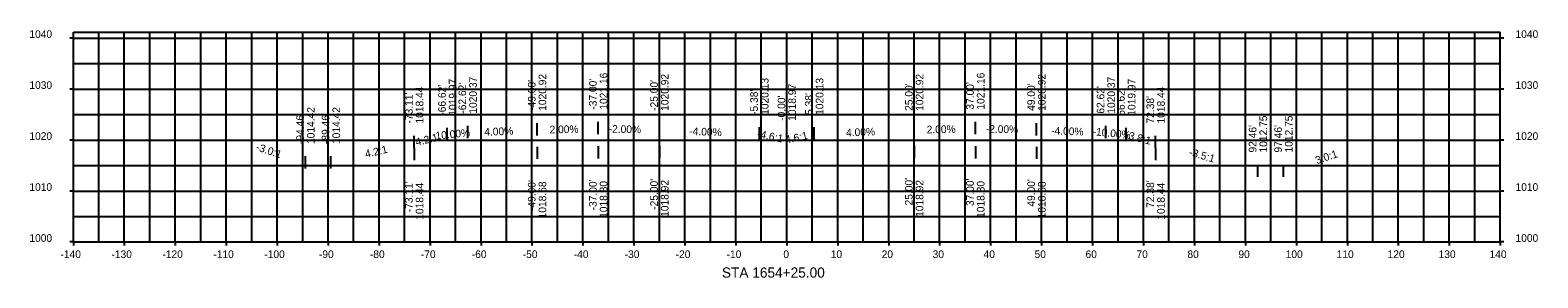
# Model space of a CAD drawing. Extents: x -148 to 147, y 993 to 1042.
import ezdxf

# ---------------------------------------------------------------- set-up
doc = ezdxf.new("R2010")
doc.units = 0
for name, color, linetype in [('SheetBorder', 7, 'Continuous'), ('SheetGridMajor', 7, 'Continuous'), ('SheetGridMinor', 7, 'Continuous'), ('SheetText', 7, 'Continuous'), ('Text', 7, 'Continuous')]:
    doc.layers.add(name, color=color, linetype=linetype)

msp = doc.modelspace()

# ---------------------------------------------------------------- linework, layer by layer
at = {"layer": 'SheetBorder'}
for p, q in [((-140, 1041.16), (140, 1041.16)), ((-140, 1000), (-140, 1041.16)), ((140, 1000), (140, 1041.16)), ((-140, 1000), (140, 1000))]:
    msp.add_line(p, q, dxfattribs=at)
at = {"layer": 'SheetGridMajor'}
for p, q in [((-140, 1040), (-140.72, 1040)), ((-140, 1040), (140, 1040)), ((-130, 1000), (-130, 1041.16)), ((-120, 1000), (-120, 1041.16)), ((-110, 1000), (-110, 1041.16)), ((-100, 1000), (-100, 1041.16)), ((-90, 1000), (-90, 1041.16)), ((-80, 1000), (-80, 1041.16)), ((-70, 1000), (-70, 1041.16)), ((-60, 1000), (-60, 1041.16)), ((-50, 1000), (-50, 1041.16)), ((-40, 1000), (-40, 1041.16)), ((-30, 1000), (-30, 1041.16)), ((-20, 1000), (-20, 1041.16)), ((-10, 1000), (-10, 1041.16)), ((0, 1000), (0, 1041.16)), ((10, 1000), (10, 1041.16)), ((20, 1000), (20, 1041.16)), ((30, 1000), (30, 1041.16)), ((40, 1000), (40, 1041.16)), ((50, 1000), (50, 1041.16)), ((60, 1000), (60, 1041.16)), ((70, 1000), (70, 1041.16)), ((80, 1000), (80, 1041.16)), ((90, 1000), (90, 1041.16)), ((100, 1000), (100, 1041.16)), ((110, 1000), (110, 1041.16)), ((120, 1000), (120, 1041.16)), ((130, 1000), (130, 1041.16)), ((140.72, 1040), (140, 1040)), ((-140, 1030), (-140.72, 1030)), ((-140, 1030), (140, 1030)), ((140.72, 1030), (140, 1030)), ((-140, 1020), (-140.72, 1020)), ((-140, 1020), (140, 1020)), ((140.72, 1020), (140, 1020)), ((-140, 1010), (-140.72, 1010)), ((-140, 1010), (140, 1010)), ((140.72, 1010), (140, 1010)), ((-140, 1000), (-140.72, 1000)), ((-140, 1000), (-140, 999.28)), ((-130, 1000), (-130, 999.28)), ((-120, 1000), (-120, 999.28)), ((-110, 1000), (-110, 999.28)), ((-100, 1000), (-100, 999.28)), ((-90, 1000), (-90, 999.28)), ((-80, 1000), (-80, 999.28)), ((-70, 1000), (-70, 999.28)), ((-60, 1000), (-60, 999.28)), ((-50, 1000), (-50, 999.28)), ((-40, 1000), (-40, 999.28)), ((-30, 1000), (-30, 999.28)), ((-20, 1000), (-20, 999.28)), ((-10, 1000), (-10, 999.28)), ((0, 1000), (0, 999.28)), ((10, 1000), (10, 999.28)), ((20, 1000), (20, 999.28)), ((30, 1000), (30, 999.28)), ((40, 1000), (40, 999.28)), ((50, 1000), (50, 999.28)), ((60, 1000), (60, 999.28)), ((70, 1000), (70, 999.28)), ((80, 1000), (80, 999.28)), ((90, 1000), (90, 999.28)), ((100, 1000), (100, 999.28)), ((110, 1000), (110, 999.28)), ((120, 1000), (120, 999.28)), ((130, 1000), (130, 999.28)), ((140, 1000), (140, 999.28)), ((140.72, 1000), (140, 1000))]:
    msp.add_line(p, q, dxfattribs=at)
at = {"layer": 'SheetGridMinor'}
for p, q in [((-135, 1000), (-135, 1041.16)), ((-125, 1000), (-125, 1041.16)), ((-115, 1000), (-115, 1041.16)), ((-105, 1000), (-105, 1041.16)), ((-95, 1000), (-95, 1041.16)), ((-85, 1000), (-85, 1041.16)), ((-75, 1000), (-75, 1041.16)), ((-65, 1000), (-65, 1041.16)), ((-55, 1000), (-55, 1041.16)), ((-45, 1000), (-45, 1041.16)), ((-35, 1000), (-35, 1041.16)), ((-25, 1000), (-25, 1041.16)), ((-15, 1000), (-15, 1041.16)), ((-5, 1000), (-5, 1041.16)), ((5, 1000), (5, 1041.16)), ((15, 1000), (15, 1041.16)), ((25, 1000), (25, 1041.16)), ((35, 1000), (35, 1041.16)), ((45, 1000), (45, 1041.16)), ((55, 1000), (55, 1041.16)), ((65, 1000), (65, 1041.16)), ((75, 1000), (75, 1041.16)), ((85, 1000), (85, 1041.16)), ((95, 1000), (95, 1041.16)), ((105, 1000), (105, 1041.16)), ((115, 1000), (115, 1041.16)), ((125, 1000), (125, 1041.16)), ((135, 1000), (135, 1041.16)), ((-140, 1035), (140, 1035)), ((-140, 1025), (140, 1025)), ((-140, 1015), (140, 1015)), ((-140, 1005), (140, 1005))]:
    msp.add_line(p, q, dxfattribs=at)
at = {"layer": 'Text'}
for p, q in [((-73.11, 1018.44), (-73.11, 1020.84)), ((-66.62, 1019.97), (-66.62, 1022.37)), ((-62.62, 1020.37), (-62.62, 1022.77)), ((-49, 1020.92), (-49, 1023.32)), ((-37, 1021.16), (-37, 1023.56)), ((-37, 1021.16), (-37, 1023.56)), ((-25, 1020.92), (-25, 1023.32)), ((-5.38, 1020.13), (-5.38, 1022.53)), ((0, 1018.97), (0, 1021.37)), ((5.38, 1020.13), (5.38, 1022.53)), ((25, 1020.92), (25, 1023.32)), ((37, 1021.16), (37, 1023.56)), ((49, 1020.92), (49, 1023.32)), ((62.62, 1020.37), (62.62, 1022.77)), ((66.62, 1019.97), (66.62, 1022.37)), ((72.38, 1018.44), (72.38, 1020.84)), ((72.38, 1018.44), (72.38, 1020.84)), ((-73.11, 1018.44), (-73.11, 1016.04)), ((-49, 1018.68), (-49, 1016.28)), ((-37, 1018.8), (-37, 1016.4)), ((-25, 1018.92), (-25, 1016.52)), ((25, 1018.92), (25, 1016.52)), ((37, 1018.8), (37, 1016.4)), ((49, 1018.68), (49, 1016.28)), ((72.38, 1018.44), (72.38, 1016.04)), ((-94.46, 1014.42), (-94.46, 1016.82)), ((-89.46, 1014.42), (-89.46, 1016.82)), ((92.46, 1012.75), (92.46, 1015.15)), ((97.46, 1012.75), (97.46, 1015.15))]:
    msp.add_line(p, q, dxfattribs=at)

# ---------------------------------------------------------------- texts
at = {"layer": 'SheetText'}
for s, height, p in [('1040', 1.5, (-148.63, 1040.03)), ('1040', 1.5, (143, 1040.03)), ('1030', 1.5, (-148.63, 1030.03)), ('1030', 1.5, (143, 1030.03)), ('1020', 1.5, (-148.63, 1020.03)), ('1020', 1.5, (143, 1020.03)), ('1010', 1.5, (-148.63, 1010.03)), ('1010', 1.5, (143, 1010.03)), ('1000', 1.5, (-148.63, 1000.03)), ('1000', 1.5, (143, 1000.03)), ('-140', 1.5, (-142.53, 996.85)), ('-130', 1.5, (-132.53, 996.85)), ('-120', 1.5, (-122.53, 996.85)), ('-110', 1.5, (-112.53, 996.85)), ('-100', 1.5, (-102.53, 996.85)), ('-90', 1.5, (-91.81, 996.85)), ('-80', 1.5, (-81.81, 996.85)), ('-70', 1.5, (-71.81, 996.85)), ('-60', 1.5, (-61.81, 996.85)), ('-50', 1.5, (-51.81, 996.85)), ('-40', 1.5, (-41.81, 996.85)), ('-30', 1.5, (-31.81, 996.85)), ('-20', 1.5, (-21.81, 996.85)), ('-10', 1.5, (-11.81, 996.85)), ('0', 1.5, (-0.67, 996.85)), ('10', 1.5, (8.62, 996.85)), ('20', 1.5, (18.62, 996.85)), ('30', 1.5, (28.62, 996.85)), ('40', 1.5, (38.62, 996.85)), ('50', 1.5, (48.62, 996.85)), ('60', 1.5, (58.62, 996.85)), ('70', 1.5, (68.62, 996.85)), ('80', 1.5, (78.62, 996.85)), ('90', 1.5, (88.62, 996.85)), ('100', 1.5, (97.9, 996.85)), ('110', 1.5, (107.9, 996.85)), ('120', 1.5, (117.9, 996.85)), ('130', 1.5, (127.9, 996.85)), ('140', 1.5, (137.9, 996.85)), ('STA 1654+25.00', 2.004, (-12.73, 993))]:
    msp.add_text(s, height=height, dxfattribs=at).set_placement(p)
at = {"layer": 'Text'}
for s, rotation, p in [('1020.92', 90, (-47.2, 1025.72)), ('1021.16', 90, (-35.2, 1025.96)), ('1021.16', 90, (-35.2, 1025.96)), ('1020.92', 90, (-23.2, 1025.72)), ('1020.92', 90, (26.8, 1025.72)), ('1021.16', 90, (38.8, 1025.96)), ('1020.92', 90, (50.8, 1025.72)), ('1018.44', 90, (-71.31, 1023.24)), ("-66.62'", 90, (-66.92, 1024.77)), ('1019.97', 90, (-64.82, 1024.77)), ("-62.62'", 90, (-62.92, 1025.17)), ('1020.37', 90, (-60.82, 1025.17)), ("-49.00'", 90, (-49.3, 1025.72)), ("-37.00'", 90, (-37.3, 1025.96)), ("-37.00'", 90, (-37.3, 1025.96)), ("-25.00'", 90, (-25.3, 1025.72)), ("-5.38'", 90, (-5.68, 1024.93)), ('1020.13', 90, (-3.58, 1024.93)), ('1018.97', 90, (1.8, 1023.77)), ('1020.13', 90, (7.18, 1024.93)), ("25.00'", 90, (24.7, 1025.72)), ("37.00'", 90, (36.7, 1025.96)), ("49.00'", 90, (48.7, 1025.72)), ("62.62'", 90, (62.32, 1025.17)), ('1020.37', 90, (64.42, 1025.17)), ("66.62'", 90, (66.32, 1024.77)), ('1019.97', 90, (68.42, 1024.77)), ('1018.44', 90, (74.18, 1023.24)), ('1018.44', 90, (74.18, 1023.24)), ("-73.11'", 90, (-73.41, 1023.24)), ("-0.00'", 90, (-0.3, 1023.77)), ("5.38'", 90, (5.08, 1024.93)), ("72.38'", 90, (72.08, 1023.24)), ("72.38'", 90, (72.08, 1023.24)), ("-94.46'", 90, (-94.76, 1019.22)), ('1014.42', 90, (-92.66, 1019.22)), ("-89.46'", 90, (-89.76, 1019.22)), ('1014.42', 90, (-87.66, 1019.22)), ('1012.75', 90, (94.26, 1017.55)), ('1012.75', 90, (99.26, 1017.55)), ('4.2:1', 13.3104, (-72.67, 1018.84)), ('10.00%', 5.7106, (-68.85, 1020.08)), ('4.00%', 2.2906, (-59.34, 1020.83)), ('2.00%', 1.1458, (-46.54, 1021.3)), ('-2.00%', 358.8542, (-34.96, 1021.45)), ('-4.00%', 357.7094, (-19.15, 1021.01)), ('-4.6:1', 347.7902, (-5.92, 1020.58)), ('4.6:1', 12.2098, (-0.13, 1019.27)), ('4.00%', 2.2906, (11.66, 1020.71)), ('2.00%', 1.1458, (27.46, 1021.3)), ('-2.00%', 358.8542, (39.04, 1021.45)), ('-4.00%', 357.7094, (51.85, 1021.13)), ('-10.00%', 354.2894, (59.96, 1020.97)), ('-3.8:1', 345.1415, (66.31, 1020.39)), ("92.46'", 90, (92.16, 1017.55)), ("97.46'", 90, (97.16, 1017.55)), ('-3.0:1', 341.5668, (-104.28, 1018.03)), ('4.2:1', 13.3096, (-82.58, 1016.5)), ('-3.5:1', 344.0554, (78.83, 1016.98)), ('3.0:1', 18.4332, (104, 1015.26)), ("-49.00'", 90, (-49.3, 1006.08)), ("-37.00'", 90, (-37.3, 1006.2)), ('1018.80', 90, (-35.2, 1004.72)), ("-25.00'", 90, (-25.3, 1006.32)), ('1018.92', 90, (-23.2, 1004.92)), ("25.00'", 90, (24.7, 1007.17)), ('1018.92', 90, (26.8, 1004.92)), ("37.00'", 90, (36.7, 1007.05)), ('1018.80', 90, (38.8, 1004.72)), ("49.00'", 90, (48.7, 1006.93)), ("72.38'", 90, (72.08, 1006.7)), ("-73.11'", 90, (-73.41, 1005.84)), ('1018.44', 90, (-71.31, 1004.36)), ('1018.68', 90, (-47.2, 1004.63)), ('1018.68', 90, (50.8, 1004.63)), ('1018.44', 90, (74.18, 1004.37))]:
    msp.add_text(s, height=1.5, rotation=rotation, dxfattribs=at).set_placement(p)

doc.saveas('drawing.dxf')
